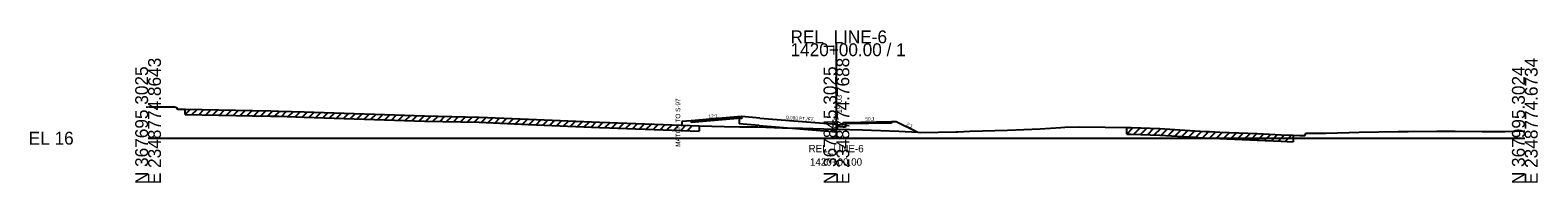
# Model space of a CAD drawing. Extents: x -26 to 403, y -10 to 6565.
# Drawn here: x -25.7 to 302.8, y 1990.3 to 2023.5 of the extents above; entities that cross this region are included whole.
import ezdxf

# ---------------------------------------------------------------- set-up
doc = ezdxf.new("R2010")
doc.units = 0
for name, color, linetype in [('RD_GPK_XS_Cell', 7, 'Continuous'), ('RD_XS_Base', 7, 'Continuous'), ('RD_XS_CurbBase', 7, 'Continuous'), ('RD_XS_CurbFront', 7, 'Continuous'), ('RD_XS_CurbTop', 7, 'Continuous'), ('RD_XS_EarthShd', 7, 'Continuous'), ('RD_XS_ExGround', 7, 'Continuous'), ('RD_XS_ExPaveRet', 7, 'Continuous'), ('RD_XS_MatchLine', 7, 'Continuous'), ('RD_XS_Pave', 7, 'Continuous'), ('RD_XS_PaveShd', 7, 'Continuous'), ('RD_XS_SW', 7, 'Continuous'), ('RD_XS_SWbase', 7, 'Continuous'), ('RD_XS_SWfront', 7, 'Continuous'), ('RD_XS_TieSlope', 7, 'Continuous'), ('RD_XS_TX_Elev_EX', 7, 'Continuous'), ('RD_XS_TX_Elev_PR', 7, 'Continuous'), ('RD_XS_TX_MatchLine', 7, 'Continuous'), ('RD_XS_TX_Slope', 7, 'Continuous'), ('RD_XS_TX_Station', 7, 'Continuous'), ('RD_XS_TX_TOC', 7, 'Continuous')]:
    doc.layers.add(name, color=color, linetype=linetype)

msp = doc.modelspace()

# ---------------------------------------------------------------- linework, layer by layer
at = {"layer": 'RD_GPK_XS_Cell'}
for p, q in [((150, 2000), (150, 2020.63)), ((0, 2000), (150, 2000)), ((150, 2000), (300, 2000))]:
    msp.add_line(p, q, dxfattribs=at)
at = {"layer": 'RD_XS_Base'}
for p, q in [((129.32, 2004.24), (128.82, 2004.28)), ((128.82, 2004.28), (128.82, 2003.09)), ((129.32, 2004.69), (129.32, 2004.24)), ((133.19, 2002.74), (128.82, 2003.09)), ((133.19, 2002.74), (150, 2001.39))]:
    msp.add_line(p, q, dxfattribs=at)
at = {"layer": 'RD_XS_CurbBase'}
for p, q in [((151.5, 2002.43), (150, 2002.51)), ((150, 2001.39), (150, 2002.51)), ((152, 2002.43), (151.5, 2002.43)), ((152, 2003.1), (152, 2002.43))]:
    msp.add_line(p, q, dxfattribs=at)
at = {"layer": 'RD_XS_CurbFront'}
msp.add_line((150, 2002.51), (150, 2003.01), dxfattribs=at)
at = {"layer": 'RD_XS_CurbTop'}
for p, q in [((150, 2003.03), (150, 2003.01)), ((150, 2003.01), (151.42, 2002.93)), ((151.42, 2002.93), (151.5, 2003.43)), ((151.5, 2003.43), (152, 2003.43))]:
    msp.add_line(p, q, dxfattribs=at)
at = {"layer": 'RD_XS_EarthShd'}
for p, q in [((118.32, 2003.77), (116.32, 2003.6)), ((162, 2003.63), (163, 2003.65))]:
    msp.add_line(p, q, dxfattribs=at)
at = {"layer": 'RD_XS_ExGround'}
msp.add_lwpolyline([(0, 2006.88), (0.3, 2006.84), (4.27, 2006.82), (5.85, 2006.8), (6.23, 2006.65), (6.4, 2006.3), (7.42, 2006.29), (8.06, 2006.29), (22.74, 2006.02), (26.73, 2005.93), (28.47, 2005.9), (34.01, 2005.71), (60.27, 2004.86), (72.13, 2004.59), (82.87, 2004.15), (98.36, 2003.49), (100.55, 2003.39), (102.39, 2003.31), (112.25, 2002.96), (120.09, 2002.71), (125.61, 2002.54), (128.94, 2002.48), (132.87, 2002.5), (138.17, 2002.26), (142.61, 2002.2), (149.45, 2001.95), (150, 2001.94), (155.71, 2001.78), (163.6, 2001.5), (167.83, 2001.28), (168.4, 2001.25), (175.99, 2001.35), (176.42, 2001.36), (179.09, 2001.5), (187.31, 2001.71), (194.38, 2002.06), (198.91, 2002.33), (199.8, 2002.39), (202.96, 2002.48), (208.55, 2002.4), (213.27, 2002.34), (214.24, 2002.3), (220.45, 2002.12), (228.1, 2001.63), (230.51, 2001.48), (231.29, 2001.44), (233.57, 2001.34), (241.7, 2000.99), (246.88, 2000.76), (249.55, 2000.63), (250.94, 2000.59), (252.05, 2000.56), (252.32, 2001.06), (252.63, 2001.06), (253.15, 2001.06), (256.61, 2001.12), (261.69, 2001.22), (263.87, 2001.31), (272.39, 2001.46), (274.56, 2001.46), (280.81, 2001.5), (284.84, 2001.53), (290.7, 2001.48), (294.93, 2001.46), (295.74, 2001.47), (300, 2001.58)], dxfattribs=at)
at = {"layer": 'RD_XS_ExPaveRet'}
for p, q in [((8.06, 2005.15), (8.06, 2006.29)), ((8.06, 2005.15), (9.18, 2006.27)), ((8.06, 2005.15), (22.74, 2004.88)), ((9.56, 2005.12), (10.68, 2006.24)), ((11.06, 2005.09), (12.18, 2006.21)), ((12.56, 2005.06), (13.68, 2006.19)), ((14.06, 2005.04), (15.18, 2006.16)), ((15.56, 2005.01), (16.68, 2006.13)), ((17.06, 2004.98), (18.18, 2006.1)), ((18.56, 2004.95), (19.68, 2006.08)), ((20.06, 2004.93), (21.18, 2006.05)), ((21.56, 2004.9), (22.68, 2006.02)), ((22.74, 2004.88), (26.73, 2004.79)), ((23.06, 2004.87), (24.18, 2005.99)), ((24.56, 2004.84), (25.68, 2005.96)), ((26.06, 2004.81), (27.18, 2005.93)), ((26.73, 2004.79), (28.47, 2004.76)), ((27.56, 2004.78), (28.68, 2005.89)), ((28.47, 2004.76), (34.01, 2004.57)), ((29.06, 2004.74), (30.17, 2005.84)), ((30.56, 2004.69), (31.67, 2005.79)), ((32.06, 2004.64), (33.17, 2005.74)), ((33.56, 2004.58), (34.67, 2005.69)), ((34.01, 2004.57), (60.27, 2003.72)), ((35.06, 2004.53), (36.17, 2005.64)), ((36.56, 2004.49), (37.67, 2005.59)), ((38.06, 2004.44), (39.17, 2005.54)), ((39.56, 2004.39), (40.67, 2005.5)), ((41.06, 2004.34), (42.17, 2005.45)), ((42.56, 2004.29), (43.67, 2005.4)), ((44.06, 2004.24), (45.17, 2005.35)), ((45.56, 2004.2), (46.67, 2005.3)), ((47.06, 2004.15), (48.17, 2005.25)), ((48.56, 2004.1), (49.67, 2005.21)), ((50.06, 2004.05), (51.17, 2005.16)), ((51.56, 2004), (52.67, 2005.11)), ((53.06, 2003.95), (54.17, 2005.06)), ((54.56, 2003.91), (55.67, 2005.01)), ((56.06, 2003.86), (57.17, 2004.96)), ((57.56, 2003.81), (58.67, 2004.92)), ((59.06, 2003.76), (60.17, 2004.87)), ((60.56, 2003.72), (61.68, 2004.83)), ((62.06, 2003.68), (63.18, 2004.8)), ((63.56, 2003.65), (64.68, 2004.76)), ((65.06, 2003.61), (66.18, 2004.73)), ((66.56, 2003.58), (67.68, 2004.69)), ((68.06, 2003.54), (69.18, 2004.66)), ((69.56, 2003.51), (70.68, 2004.62)), ((71.06, 2003.47), (72.18, 2004.59)), ((72.56, 2003.43), (73.66, 2004.53)), ((74.06, 2003.37), (75.16, 2004.46)), ((75.56, 2003.3), (76.66, 2004.4)), ((77.06, 2003.24), (78.16, 2004.34)), ((78.56, 2003.18), (79.66, 2004.28)), ((80.06, 2003.12), (81.16, 2004.22)), ((81.56, 2003.06), (82.66, 2004.15)), ((83.06, 2002.99), (84.16, 2004.09)), ((60.27, 2003.72), (72.13, 2003.45)), ((72.13, 2003.45), (82.87, 2003)), ((82.87, 2003), (98.36, 2002.34)), ((84.56, 2002.93), (85.66, 2004.03)), ((86.06, 2002.87), (87.16, 2003.96)), ((87.56, 2002.8), (88.66, 2003.9)), ((89.06, 2002.74), (90.16, 2003.84)), ((90.56, 2002.68), (91.66, 2003.77)), ((92.06, 2002.61), (93.16, 2003.71)), ((93.56, 2002.55), (94.66, 2003.64)), ((95.06, 2002.48), (96.16, 2003.58)), ((96.56, 2002.42), (97.66, 2003.52)), ((98.06, 2002.36), (99.16, 2003.45)), ((98.36, 2002.34), (100.55, 2002.25)), ((99.56, 2002.29), (100.66, 2003.39)), ((100.55, 2002.25), (102.39, 2002.17)), ((101.06, 2002.23), (102.16, 2003.32)), ((102.39, 2002.17), (112.25, 2001.82)), ((102.56, 2002.16), (103.67, 2003.26)), ((104.06, 2002.11), (105.17, 2003.21)), ((105.56, 2002.05), (106.67, 2003.16)), ((107.06, 2002), (108.17, 2003.1)), ((108.56, 2001.95), (109.67, 2003.05)), ((110.06, 2001.89), (111.17, 2003)), ((111.56, 2001.84), (112.67, 2002.95)), ((112.25, 2001.82), (120.09, 2001.56)), ((113.06, 2001.79), (114.17, 2002.9)), ((114.56, 2001.74), (115.67, 2002.85)), ((116.06, 2001.69), (117.17, 2002.8)), ((117.56, 2001.65), (118.67, 2002.75)), ((120.09, 2002.71), (120.09, 2001.56)), ((213.27, 2000.91), (213.27, 2002.34)), ((213.27, 2000.91), (214.64, 2002.29)), ((213.27, 2000.91), (214.24, 2000.86)), ((214.24, 2000.86), (220.45, 2000.69)), ((214.77, 2000.85), (216.16, 2002.24)), ((216.27, 2000.8), (217.66, 2002.2)), ((217.77, 2000.76), (219.16, 2002.16)), ((219.27, 2000.72), (220.66, 2002.11)), ((220.77, 2000.67), (222.11, 2002.02)), ((222.27, 2000.57), (223.61, 2001.92)), ((223.77, 2000.47), (225.11, 2001.82)), ((225.27, 2000.37), (226.61, 2001.72)), ((226.77, 2000.28), (228.11, 2001.63)), ((228.27, 2000.18), (229.62, 2001.53)), ((229.77, 2000.09), (231.13, 2001.45)), ((231.27, 2000.01), (232.64, 2001.38)), ((232.77, 1999.94), (234.14, 2001.32)), ((234.27, 1999.88), (235.64, 2001.25)), ((235.77, 1999.81), (237.14, 2001.19)), ((237.27, 1999.74), (238.64, 2001.12)), ((238.77, 1999.68), (240.14, 2001.05)), ((240.27, 1999.61), (241.64, 2000.99)), ((241.77, 1999.55), (243.14, 2000.92)), ((243.27, 1999.48), (244.64, 2000.86)), ((244.77, 1999.42), (246.14, 2000.79)), ((220.45, 2000.69), (228.1, 2000.19)), ((228.1, 2000.19), (230.51, 2000.04)), ((230.51, 2000.04), (231.29, 2000.01)), ((231.29, 2000.01), (233.57, 1999.91)), ((233.57, 1999.91), (241.7, 1999.55)), ((241.7, 1999.55), (246.88, 1999.33)), ((246.27, 1999.35), (247.64, 2000.73)), ((246.88, 1999.33), (249.55, 1999.2)), ((247.77, 1999.28), (249.14, 2000.65)), ((249.55, 2000.63), (249.55, 1999.2))]:
    msp.add_line(p, q, dxfattribs=at)
at = {"layer": 'RD_XS_MatchLine'}
msp.add_line((116.32, 2003.6), (116.32, 2002.83), dxfattribs=at)
at = {"layer": 'RD_XS_Pave'}
msp.add_line((133.32, 2004.37), (150, 2003.03), dxfattribs=at)
at = {"layer": 'RD_XS_PaveShd'}
msp.add_line((133.32, 2004.37), (129.32, 2004.69), dxfattribs=at)
at = {"layer": 'RD_XS_SW'}
for p, q in [((129.32, 2004.69), (118.32, 2003.77)), ((152, 2003.43), (162, 2003.63))]:
    msp.add_line(p, q, dxfattribs=at)
at = {"layer": 'RD_XS_SWbase'}
for p, q in [((129.32, 2004.35), (118.32, 2003.44)), ((129.32, 2004.69), (129.32, 2004.35)), ((118.32, 2003.77), (118.32, 2003.44)), ((162, 2003.3), (152, 2003.1)), ((162, 2003.63), (162, 2003.3))]:
    msp.add_line(p, q, dxfattribs=at)
at = {"layer": 'RD_XS_SWfront'}
msp.add_line((152, 2003.43), (152, 2003.1), dxfattribs=at)
at = {"layer": 'RD_XS_TieSlope'}
msp.add_line((163, 2003.65), (167.74, 2001.28), dxfattribs=at)

# ---------------------------------------------------------------- texts
at = {"layer": 'RD_GPK_XS_Cell'}
for s, p in [('1420+00.00 / 1', (140, 2017.83)), ('REL_LINE-6', (140, 2020.63)), ('EL 16', (-26, 1998.6))]:
    msp.add_text(s, height=2.8, dxfattribs=at).set_placement(p)
for s, p in [('E 2348774.8643', (2.8, 1990)), ('E 2348774.7688', (152.8, 1990)), ('E 2348774.6734', (302.8, 1990)), ('N 367695.3025', (0, 1990)), ('N 367845.3025', (150, 1990)), ('N 367995.3024', (300, 1990))]:
    msp.add_text(s, height=2.8, rotation=90, dxfattribs=at).set_placement(p)
at = {"layer": 'RD_XS_TX_Elev_EX'}
msp.add_text('17.94', height=1, rotation=90, dxfattribs=at).set_placement((150.5, 2001.94))
at = {"layer": 'RD_XS_TX_Elev_PR'}
msp.add_text(' 19.03', height=1.2, rotation=90, dxfattribs=at).set_placement((151.2, 2004.96))
at = {"layer": 'RD_XS_TX_MatchLine'}
msp.add_text('MATCH TO S-97', height=1, rotation=90, dxfattribs=at).set_placement((115.97, 1998.12))
at = {"layer": 'RD_XS_TX_Slope'}
for s, rotation, p in [('12:1', 4.7636, (122.14, 2004.33)), ('0.080 FT./FT.', 355.4279, (139, 2004.16)), ('50:1', 1.1458, (156.3, 2003.81)), ('2:1', 333.4349, (165.14, 2002.8))]:
    msp.add_text(s, height=0.75, rotation=rotation, dxfattribs=at).set_placement(p)
at = {"layer": 'RD_XS_TX_Station'}
for s, p in [('REL_LINE-6', (143.92, 1996.93)), ('1420+00.00', (144.23, 1994.03))]:
    msp.add_text(s, height=1.6, dxfattribs=at).set_placement(p)
at = {"layer": 'RD_XS_TX_TOC'}
msp.add_text('TOCRT', height=0.05, dxfattribs=at).set_placement((151.22, 2003.38))

doc.saveas('drawing.dxf')
